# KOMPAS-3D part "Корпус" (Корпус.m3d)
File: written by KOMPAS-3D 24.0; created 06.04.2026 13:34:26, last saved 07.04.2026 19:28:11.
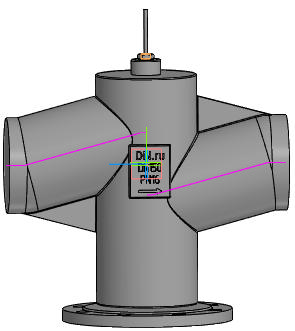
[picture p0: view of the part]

Document properties: Автор: R2D2; Полное имя файла: E:\Работа\Зайцев\Солянка\VSR1-13V-PED-F Клапан запорно-регулирующий DN.ru\DN150\исходные материалы\Корпус.m3d

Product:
- Body: Труба / Нестандартная труба / L = 241.9 мм  | qty 1
    Материал: Нестандартная труба (density 7856 kg/m3)
    Масса: 122.463743
    Раздел спецификации: Детали
    Примечание: 38,2 кг
    additional columns: Pipeline; 0.16; 0; 0; 0.002; 0.24186; true; 0.04
- Body: Труба / Нестандартная труба / L = 241.9 мм  | qty 1
    Материал: Нестандартная труба (density 7856 kg/m3)
    Масса: 122.463743
    Раздел спецификации: Детали
    Форматы листов документа: БЧ
    Примечание: 38,2 кг
    additional columns: Pipeline; 0.16; 0; 0; 0.002; 0.24186; true; 0.04
- Component [standard]: Гайка М16-6H ГОСТ 5916-70  | qty 1  | Масса: 0.01768; Рассекать на разрезах: no; source file: C:\Program Files\ASCON\KOMPAS-3D v24\Libs\PolynomLib\DATA\vault\Methods\Kompas\3D\PLib_Nut_OST92_900.m3d
- Component [standard]: (unnamed)  | qty 1  | Материал: ВЧ40 ГОСТ 7293-85 (density 7200 kg/m3); Масса: 9.095237; Рассекать на разрезах: no; additional columns: 150-16-B-2-ВЧ40-II; Заглушка; ГОСТ 34785-2021
- Body: Тело 4  | qty 1
    Материал: Нестандартная труба (density 7856 kg/m3)
    Масса: 122.463743
- Part/product: Корпус
    Масса: 6.9

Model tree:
1. Эскиз:1
2. Труба:1  (labels: {F703FF30-5BE6-4673-A7F1-8EDA1BE1E2D1}; SHAPEOBJECT3D_ATTR_BUTT; SHAPEOBJECT3D_ATTR_VALID; SHAPEOBJECT3D_ATTR_BUTT_AREA)
     PIPE_R = 7
3. Труба:2  (labels: {F703FF30-5BE6-4673-A7F1-8EDA1BE1E2D1}; SHAPEOBJECT3D_ATTR_BUTT; SHAPEOBJECT3D_ATTR_VALID; SHAPEOBJECT3D_ATTR_BUTT_AREA)
     PIPE_R = 7
4. Эскиз:2
5. Элемент выдавливания:1
     Расстояние 1 = 176; Смещение 1 = -1; Расстояние 2 = 235; Смещение 2 = -5
6. РЕБРО  (with: Ребро.Труба:1, Грань.Элемент выдавливания:1, Грань.Труба:1, Грань.Труба:2)
7. Элемент выдавливания:2
     Расстояние 1 = 8
8. Эскиз:4  (with: Грань.Элемент выдавливания:1)
9. Скругление:3  (with: Ребро.Элемент выдавливания:2)
10. Элемент выдавливания:3
     Расстояние 1 = 1
11. Эскиз:5  (with: Грань.Элемент выдавливания:3)
12. Элемент выдавливания:4
     Расстояние 1 = 7.5; Смещение 1 = 0.5
13. ШТОК
14. Элемент выдавливания:5
15. ОТЛИВКА
16. Скругление:6  (with: Грань.Элемент выдавливания:1)
17. Элемент выдавливания:6  (with: Грань.Элемент выдавливания:1)
     Смещение 1 = 4
18. ТЕКСТ  (with: Грань.Элемент выдавливания:6)
19. Элемент выдавливания:7
     Расстояние 1 = 0.5
20. Скругление:7  (with: Ребро.Элемент выдавливания:6)
     Радиус = 2
21. Эскиз:9  (with: Грань.Элемент выдавливания:1, Ребро.Скругление:6, Ребро.Элемент выдавливания:5)
22. Элемент вращения:1
     Угол 1 = 360
23. Скругление:8  (with: Ребро.Элемент вращения:1, Грань.Элемент выдавливания:3)
     Радиус = 2

Expressions: DS/2+3; v22*2
Referenced files in C:\Program Files\ASCON\KOMPAS-3D v24\Libs\Pipeline\: StylesTemplate.a3d, TemplateHPH, InsulationStylesTemplate.a3d, Insulation
Referenced files in C:\Program Files\ASCON\KOMPAS-3D v24\Templates\: Констр. чертеж А3 гориз. перв. лист.cdt
Referenced files in E:\Работа\Зайцев\Солянка\VSR1-13V-PED-F Клапан запорно-регулирующий DN.ru\DN15\DN15 Kv0.16\исходные материалы\: 
Referenced files in C:\Program Files\ASCON\KOMPAS-3D v24\Libs\PolynomLib\DATA\vault\Methods\Kompas\3D\: PLib_Nut_OST92_900.m3d, PLib_Flange_Blind_GOST_34785_2100.m3d
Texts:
  Отводы ГОСТ 17375-2001
  Констр. чертеж А3 гориз. перв. лист.cdt
  BOSimple***PART:2c8e7818-1586-f79e-db7d-bc045ba468e4***SHORTLOC:Root±30±10±20±©{}110±10±50±80[Нет;Без покрытия;Без указания материала;-;16;2;24]
  BOSimple***Material:38d6725a-5efe-48e1-b177-a7817acb862a
  BOSimple***PART:44a07c0b-53bc-fd34-22b6-4ce709166853***SHORTLOC:B619_EF039B503CC34112[2;16;150;Круглая;II;ВЧ40 ГОСТ 7293-85]
  var3D
  PN16
  LL-10
  DN+10
  bcut1
  hole1
  hcut1
  hole2
  cut1
  Труба / Нестандартная труба / L = %s мм
  Plane. Начало координат
  Ось Y.Начало координат
  Плоскость ZX.Начало координат
  Горизонтальная плоскость. Начало координат
  Плоскость XY.Начало координат
  Плоскость ZY.Начало координат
